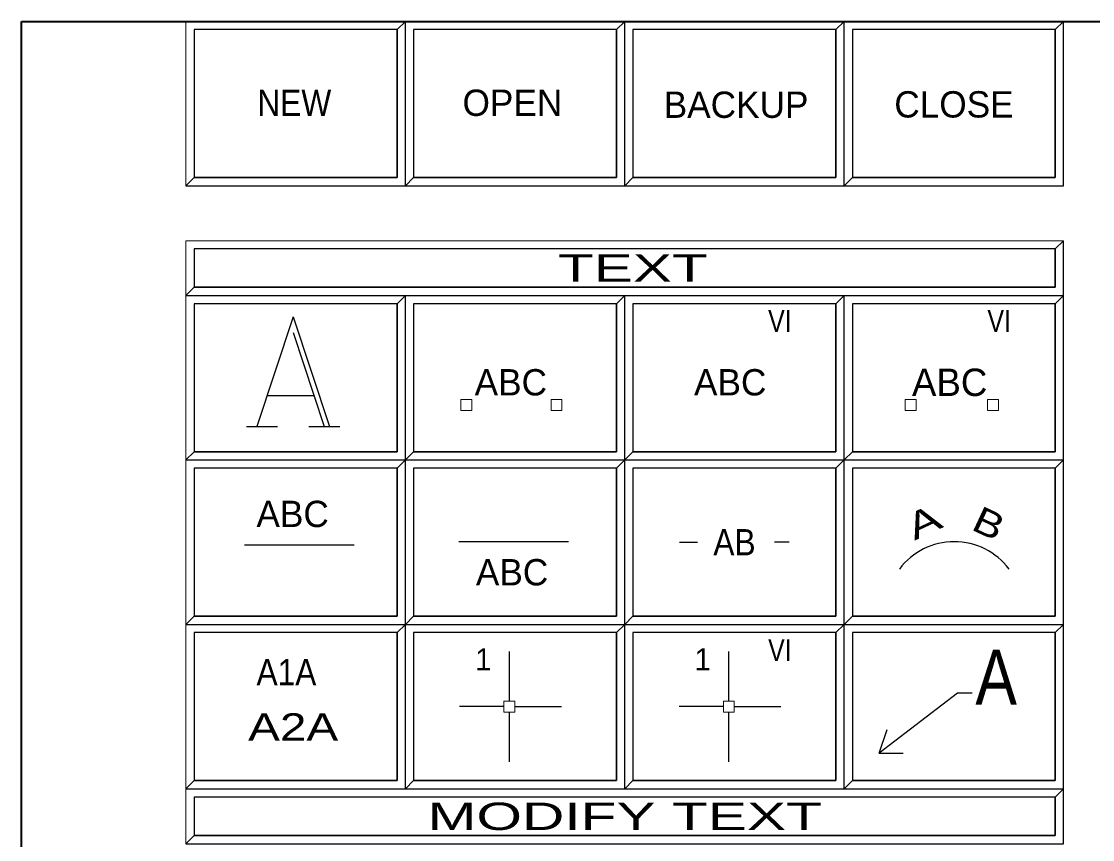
# Model space of a CAD drawing. Extents: x 95906.8 to 95923.6, y 90964.8 to 90972.8.
# Drawn here: x 95906.832 to 95908.785, y 90971.269 to 90972.762 of the extents above; entities that cross this region are included whole.
import ezdxf
from ezdxf.enums import TextEntityAlignment as Align

# ---------------------------------------------------------------- set-up
doc = ezdxf.new("R2010")
doc.units = 0
doc.header["$LTSCALE"] = 0.019
for name, color, linetype, lineweight in [('11', 7, 'Continuous', 25), ('12', 7, 'Continuous', 25), ('17', 7, 'Continuous', 25), ('18', 7, 'Continuous', 25), ('2', 7, 'Continuous', 13), ('3', 7, 'Continuous', 25), ('6', 7, 'Continuous', 25), ('7', 7, 'Continuous', 35)]:
    doc.layers.add(name, color=color, linetype=linetype, lineweight=lineweight)

msp = doc.modelspace()

# ---------------------------------------------------------------- linework, layer by layer
at = {"layer": '11'}
for points in [[(95907.1473, 90972.4767), (95907.5173, 90972.4767), (95907.5173, 90972.7467), (95907.1473, 90972.7467)], [(95907.5473, 90972.4767), (95907.9173, 90972.4767), (95907.9173, 90972.7467), (95907.5473, 90972.7467)], [(95907.9473, 90972.4767), (95908.3173, 90972.4767), (95908.3173, 90972.7467), (95907.9473, 90972.7467)], [(95908.3473, 90972.4767), (95908.7173, 90972.4767), (95908.7173, 90972.7467), (95908.3473, 90972.7467)], [(95907.5473, 90971.9767), (95907.9173, 90971.9767), (95907.9173, 90972.2467), (95907.5473, 90972.2467)], [(95907.9473, 90971.9767), (95908.3173, 90971.9767), (95908.3173, 90972.2467), (95907.9473, 90972.2467)], [(95908.3473, 90971.9767), (95908.7173, 90971.9767), (95908.7173, 90972.2467), (95908.3473, 90972.2467)], [(95907.1473, 90971.6767), (95907.5173, 90971.6767), (95907.5173, 90971.9467), (95907.1473, 90971.9467)], [(95907.5473, 90971.6767), (95907.9173, 90971.6767), (95907.9173, 90971.9467), (95907.5473, 90971.9467)], [(95907.9473, 90971.6767), (95908.3173, 90971.6767), (95908.3173, 90971.9467), (95907.9473, 90971.9467)], [(95908.3473, 90971.6767), (95908.7173, 90971.6767), (95908.7173, 90971.9467), (95908.3473, 90971.9467)], [(95907.1473, 90971.3767), (95907.5173, 90971.3767), (95907.5173, 90971.6467), (95907.1473, 90971.6467)], [(95907.5473, 90971.3767), (95907.9173, 90971.3767), (95907.9173, 90971.6467), (95907.5473, 90971.6467)], [(95907.9473, 90971.3767), (95908.3173, 90971.3767), (95908.3173, 90971.6467), (95907.9473, 90971.6467)], [(95908.3473, 90971.3767), (95908.7173, 90971.3767), (95908.7173, 90971.6467), (95908.3473, 90971.6467)]]:
    msp.add_lwpolyline(points, close=True, dxfattribs=at)
at = {"layer": '12'}
msp.add_lwpolyline([(95907.1473, 90971.9767), (95907.5173, 90971.9767), (95907.5173, 90972.2467), (95907.1473, 90972.2467)], close=True, dxfattribs=at)
at = {"layer": '17'}
msp.add_lwpolyline([(95907.1473, 90972.2767), (95908.7173, 90972.2767), (95908.7173, 90972.3467), (95907.1473, 90972.3467)], close=True, dxfattribs=at)
at = {"layer": '18'}
msp.add_lwpolyline([(95907.1473, 90971.2767), (95908.7173, 90971.2767), (95908.7173, 90971.3467), (95907.1473, 90971.3467)], close=True, dxfattribs=at)
at = {"layer": '2'}
for points in [[(95907.1323, 90972.7617), (95907.1323, 90972.4617), (95907.1473, 90972.4767), (95907.1473, 90972.7467), (95907.5173, 90972.7467), (95907.5323, 90972.7617)], [(95907.5323, 90972.7617), (95907.5323, 90972.4617), (95907.5473, 90972.4767), (95907.5473, 90972.7467), (95907.9173, 90972.7467), (95907.9323, 90972.7617)], [(95907.9323, 90972.7617), (95907.9323, 90972.4617), (95907.9473, 90972.4767), (95907.9473, 90972.7467), (95908.3173, 90972.7467), (95908.3323, 90972.7617)], [(95908.3323, 90972.7617), (95908.3323, 90972.4617), (95908.3473, 90972.4767), (95908.3473, 90972.7467), (95908.7173, 90972.7467), (95908.7323, 90972.7617)], [(95907.1323, 90972.3617), (95907.1323, 90972.2617), (95907.1473, 90972.2767), (95907.1473, 90972.3467), (95908.7173, 90972.3467), (95908.7323, 90972.3617)], [(95907.1323, 90972.2617), (95907.1323, 90971.9617), (95907.1473, 90971.9767), (95907.1473, 90972.2467), (95907.5173, 90972.2467), (95907.5323, 90972.2617)], [(95907.5323, 90972.2617), (95907.5323, 90971.9617), (95907.5473, 90971.9767), (95907.5473, 90972.2467), (95907.9173, 90972.2467), (95907.9323, 90972.2617)], [(95907.9323, 90972.2617), (95907.9323, 90971.9617), (95907.9473, 90971.9767), (95907.9473, 90972.2467), (95908.3173, 90972.2467), (95908.3323, 90972.2617)], [(95908.3323, 90972.2617), (95908.3323, 90971.9617), (95908.3473, 90971.9767), (95908.3473, 90972.2467), (95908.7173, 90972.2467), (95908.7323, 90972.2617)], [(95907.1323, 90971.9617), (95907.1323, 90971.6617), (95907.1473, 90971.6767), (95907.1473, 90971.9467), (95907.5173, 90971.9467), (95907.5323, 90971.9617)], [(95907.5323, 90971.9617), (95907.5323, 90971.6617), (95907.5473, 90971.6767), (95907.5473, 90971.9467), (95907.9173, 90971.9467), (95907.9323, 90971.9617)], [(95907.9323, 90971.9617), (95907.9323, 90971.6617), (95907.9473, 90971.6767), (95907.9473, 90971.9467), (95908.3173, 90971.9467), (95908.3323, 90971.9617)], [(95908.3323, 90971.9617), (95908.3323, 90971.6617), (95908.3473, 90971.6767), (95908.3473, 90971.9467), (95908.7173, 90971.9467), (95908.7323, 90971.9617)], [(95907.1323, 90971.6617), (95907.1323, 90971.3617), (95907.1473, 90971.3767), (95907.1473, 90971.6467), (95907.5173, 90971.6467), (95907.5323, 90971.6617)], [(95907.5323, 90971.6617), (95907.5323, 90971.3617), (95907.5473, 90971.3767), (95907.5473, 90971.6467), (95907.9173, 90971.6467), (95907.9323, 90971.6617)], [(95907.9323, 90971.6617), (95907.9323, 90971.3617), (95907.9473, 90971.3767), (95907.9473, 90971.6467), (95908.3173, 90971.6467), (95908.3323, 90971.6617)], [(95908.3323, 90971.6617), (95908.3323, 90971.3617), (95908.3473, 90971.3767), (95908.3473, 90971.6467), (95908.7173, 90971.6467), (95908.7323, 90971.6617)], [(95907.1323, 90971.3617), (95907.1323, 90971.2617), (95907.1473, 90971.2767), (95907.1473, 90971.3467), (95908.7173, 90971.3467), (95908.7323, 90971.3617)]]:
    msp.add_lwpolyline(points, close=True, dxfattribs=at)
at = {"layer": '3'}
for points in [[(95907.1323, 90972.4617), (95907.5323, 90972.4617), (95907.5323, 90972.7617), (95907.5173, 90972.7467), (95907.5173, 90972.4767), (95907.1473, 90972.4767)], [(95907.5323, 90972.4617), (95907.9323, 90972.4617), (95907.9323, 90972.7617), (95907.9173, 90972.7467), (95907.9173, 90972.4767), (95907.5473, 90972.4767)], [(95907.9323, 90972.4617), (95908.3323, 90972.4617), (95908.3323, 90972.7617), (95908.3173, 90972.7467), (95908.3173, 90972.4767), (95907.9473, 90972.4767)], [(95908.3323, 90972.4617), (95908.7323, 90972.4617), (95908.7323, 90972.7617), (95908.7173, 90972.7467), (95908.7173, 90972.4767), (95908.3473, 90972.4767)], [(95907.1323, 90972.2617), (95908.7323, 90972.2617), (95908.7323, 90972.3617), (95908.7173, 90972.3467), (95908.7173, 90972.2767), (95907.1473, 90972.2767)], [(95907.1323, 90971.9617), (95907.5323, 90971.9617), (95907.5323, 90972.2617), (95907.5173, 90972.2467), (95907.5173, 90971.9767), (95907.1473, 90971.9767)], [(95907.5323, 90971.9617), (95907.9323, 90971.9617), (95907.9323, 90972.2617), (95907.9173, 90972.2467), (95907.9173, 90971.9767), (95907.5473, 90971.9767)], [(95907.9323, 90971.9617), (95908.3323, 90971.9617), (95908.3323, 90972.2617), (95908.3173, 90972.2467), (95908.3173, 90971.9767), (95907.9473, 90971.9767)], [(95908.3323, 90971.9617), (95908.7323, 90971.9617), (95908.7323, 90972.2617), (95908.7173, 90972.2467), (95908.7173, 90971.9767), (95908.3473, 90971.9767)], [(95907.1323, 90971.6617), (95907.5323, 90971.6617), (95907.5323, 90971.9617), (95907.5173, 90971.9467), (95907.5173, 90971.6767), (95907.1473, 90971.6767)], [(95907.5323, 90971.6617), (95907.9323, 90971.6617), (95907.9323, 90971.9617), (95907.9173, 90971.9467), (95907.9173, 90971.6767), (95907.5473, 90971.6767)], [(95907.9323, 90971.6617), (95908.3323, 90971.6617), (95908.3323, 90971.9617), (95908.3173, 90971.9467), (95908.3173, 90971.6767), (95907.9473, 90971.6767)], [(95908.3323, 90971.6617), (95908.7323, 90971.6617), (95908.7323, 90971.9617), (95908.7173, 90971.9467), (95908.7173, 90971.6767), (95908.3473, 90971.6767)], [(95907.1323, 90971.3617), (95907.5323, 90971.3617), (95907.5323, 90971.6617), (95907.5173, 90971.6467), (95907.5173, 90971.3767), (95907.1473, 90971.3767)], [(95907.5323, 90971.3617), (95907.9323, 90971.3617), (95907.9323, 90971.6617), (95907.9173, 90971.6467), (95907.9173, 90971.3767), (95907.5473, 90971.3767)], [(95907.9323, 90971.3617), (95908.3323, 90971.3617), (95908.3323, 90971.6617), (95908.3173, 90971.6467), (95908.3173, 90971.3767), (95907.9473, 90971.3767)], [(95908.3323, 90971.3617), (95908.7323, 90971.3617), (95908.7323, 90971.6617), (95908.7173, 90971.6467), (95908.7173, 90971.3767), (95908.3473, 90971.3767)], [(95907.1323, 90971.2617), (95908.7323, 90971.2617), (95908.7323, 90971.3617), (95908.7173, 90971.3467), (95908.7173, 90971.2767), (95907.1473, 90971.2767)]]:
    msp.add_lwpolyline(points, close=True, dxfattribs=at)
at = {"layer": '6'}
for p, q in [((95907.3278, 90972.2225), (95907.2617, 90972.0225)), ((95907.3278, 90972.2225), (95907.394, 90972.0225)), ((95907.3278, 90972.1942), (95907.3845, 90972.0225)), ((95907.2806, 90972.0792), (95907.3656, 90972.0792)), ((95907.2428, 90972.0225), (95907.2995, 90972.0225)), ((95907.3562, 90972.0225), (95907.4129, 90972.0225)), ((95907.239, 90971.8071), (95907.439, 90971.8071)), ((95907.6297, 90971.8127), (95907.8297, 90971.8127)), ((95908.0323, 90971.8117), (95908.0648, 90971.8117)), ((95908.2323, 90971.8117), (95908.2054, 90971.8117)), ((95907.7221, 90971.5218), (95907.7221, 90971.6124)), ((95908.1221, 90971.5218), (95908.1221, 90971.6124)), ((95907.7121, 90971.5118), (95907.6313, 90971.5118)), ((95907.7221, 90971.4112), (95907.7221, 90971.5018)), ((95907.7321, 90971.5118), (95907.8171, 90971.5118)), ((95908.1121, 90971.5118), (95908.0313, 90971.5118)), ((95908.1221, 90971.4112), (95908.1221, 90971.5018)), ((95908.1321, 90971.5118), (95908.2171, 90971.5118)), ((95908.3963, 90971.4268), (95908.4397, 90971.4268))]:
    msp.add_line(p, q, dxfattribs=at)
at = {"layer": '6', "lineweight": 13}
for points in [[(95907.6336, 90972.0522), (95907.6536, 90972.0522), (95907.6536, 90972.0722), (95907.6336, 90972.0722)], [(95907.7979, 90972.0522), (95907.8179, 90972.0522), (95907.8179, 90972.0722), (95907.7979, 90972.0722)], [(95908.4434, 90972.0522), (95908.4634, 90972.0522), (95908.4634, 90972.0722), (95908.4434, 90972.0722)], [(95908.5935, 90972.0522), (95908.6135, 90972.0522), (95908.6135, 90972.0722), (95908.5935, 90972.0722)], [(95907.7121, 90971.5018), (95907.7321, 90971.5018), (95907.7321, 90971.5218), (95907.7121, 90971.5218)], [(95908.1121, 90971.5018), (95908.1321, 90971.5018), (95908.1321, 90971.5218), (95908.1121, 90971.5218)]]:
    msp.add_lwpolyline(points, close=True, dxfattribs=at)
at = {"layer": '6'}
msp.add_lwpolyline([(95908.5659, 90971.5364), (95908.539, 90971.5364), (95908.3963, 90971.4268), (95908.4108, 90971.4702)], dxfattribs=at)
msp.add_arc((95908.5331, 90971.6876), 0.125, 36.8699, 143.1301, dxfattribs=at)
at = {"layer": '7'}
msp.add_lwpolyline([(95906.8323, 90972.7617), (95918.8323, 90972.7617), (95918.8323, 90964.7617), (95906.8323, 90964.7617)], close=True, dxfattribs=at)

# ---------------------------------------------------------------- texts
at = {"layer": '6'}
for s, height, width, p in [('NEW', 0.048, 0.9, (95907.3298, 90972.5893)), ('VI', 0.04, 0.85, (95908.2152, 90972.1953)), ('VI', 0.04, 0.85, (95908.6151, 90972.1953)), ('AB', 0.048, 0.9, (95908.1324, 90971.7877)), ('VI', 0.04, 0.85, (95908.2152, 90971.5948)), ('A', 0.1, 0.85, (95908.6095, 90971.5154)), ('A1A', 0.048, 0.9, (95907.3155, 90971.5506)), (' A2A', 0.05, 1.3, (95907.3157, 90971.4496))]:
    msp.add_text(s, height=height, dxfattribs=dict(at, width=width)).set_placement(p, align=Align.CENTER)
for s, height, p in [('OPEN', 0.048, (95907.7275, 90972.5893)), ('BACKUP', 0.048, (95908.1353, 90972.5857)), ('CLOSE', 0.048, (95908.5326, 90972.5864)), ('ABC', 0.048, (95907.7246, 90972.0794)), ('ABC', 0.048, (95908.1246, 90972.0794)), ('ABC', 0.04999, (95908.5247, 90972.0784)), ('ABC', 0.048, (95907.3268, 90971.8393)), ('ABC', 0.048, (95907.7269, 90971.7329)), ('1', 0.04, (95907.6745, 90971.5781)), ('1', 0.04, (95908.0745, 90971.5781))]:
    msp.add_text(s, height=height, dxfattribs=at).set_placement(p, align=Align.CENTER)
for s, rotation, width, p in [('B', 335, 1.25, (95908.5861, 90971.8243)), ('A', 25, 1.4, (95908.4877, 90971.827))]:
    msp.add_text(s, height=0.048, rotation=rotation, dxfattribs=dict(at, width=width)).set_placement(p, align=Align.CENTER)
at = {"layer": '7', "width": 1.6}
for s, p in [('          TEXT         ', (95907.9322, 90972.2867)), ('      MODIFY TEXT      ', (95907.9322, 90971.2867))]:
    msp.add_text(s, height=0.04999, dxfattribs=at).set_placement(p, align=Align.CENTER)

doc.saveas('drawing.dxf')
